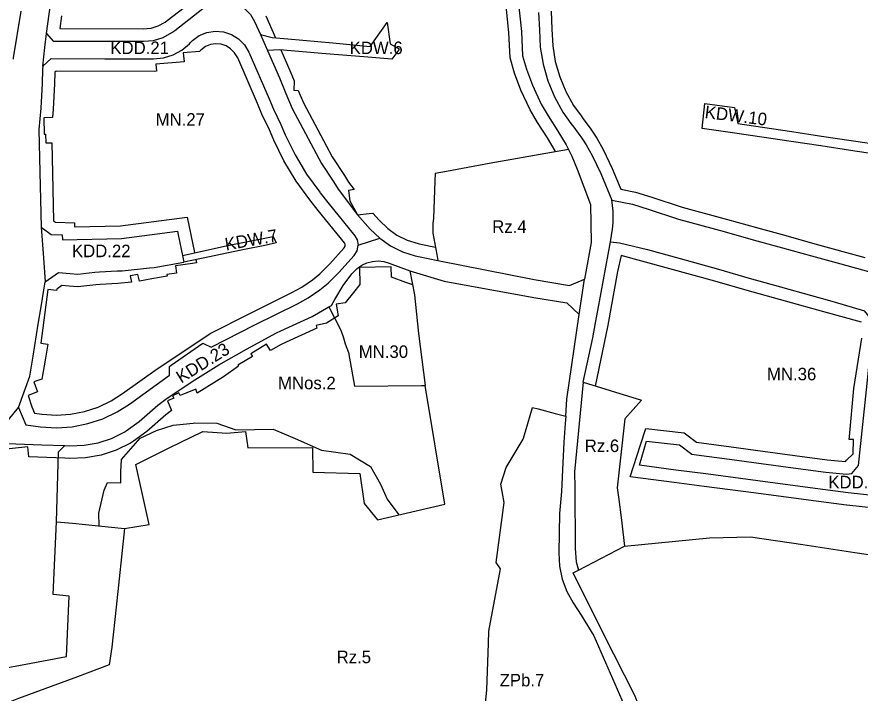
# Model space of a CAD drawing. Extents: x 7414808 to 7417449, y 5544732 to 5546764.
# Drawn here: x 7415895.6 to 7416232.5, y 5545469 to 5545739 of the extents above; entities that cross this region are included whole.
import ezdxf

# ---------------------------------------------------------------- set-up
doc = ezdxf.new("R2010")
doc.units = 0
for name, color, linetype in [('LIN_Linie Rozgraniczajace', 7, 'Continuous'), ('LIN_nieprzekraczale linie zabudowy', 7, 'Continuous'), ('TXT_Oznaczenia Przeznaczenia', 7, 'Continuous')]:
    doc.layers.add(name, color=color, linetype=linetype)

msp = doc.modelspace()

# ---------------------------------------------------------------- linework, layer by layer
at = {"layer": 'LIN_Linie Rozgraniczajace'}
for p, q in [((7415992.94, 5545731.87), (7415995.76, 5545725.48)), ((7416120.04, 5545518.08), (7416138.44, 5545527.72))]:
    msp.add_line(p, q, dxfattribs=at)
for points in [[(7415907.51, 5545732.31), (7415908.48, 5545740.08), (7415910.18, 5545751.57), (7415912.74, 5545763.6), (7415920.96, 5545779.17), (7415933.01, 5545796.09), (7415954.12, 5545809.43), (7415968.5, 5545818.52)], [(7416081.41, 5545803.58), (7416088.85, 5545770.68), (7416091.67, 5545762.78), (7416096.02, 5545744.11), (7416097.23, 5545733.11), (7416097.68, 5545723.46), (7416099.22, 5545718.1), (7416101.6, 5545711.67), (7416105.11, 5545704.09), (7416107.85, 5545699.39), (7416111.82, 5545693.27), (7416115.05, 5545687.84), (7416115.96, 5545686.02)], [(7415907.51, 5545732.31), (7415910.16, 5545729.3), (7415930.83, 5545729.24), (7415946.27, 5545729.2), (7415950.24, 5545729.58), (7415954.06, 5545730.75), (7415957.57, 5545732.66), (7415958.68, 5545733.47), (7415969.92, 5545742.3), (7415971.21, 5545743.2), (7415974.2, 5545744.56), (7415975.03, 5545744.8), (7415981.8, 5545744.72), (7415983.83, 5545743.99), (7415986.63, 5545742.29), (7415988.94, 5545739.96), (7415990.61, 5545737.14), (7415992.94, 5545731.87)], [(7415894.25, 5545722.05), (7415894.28, 5545722.62), (7415897.34, 5545741.25)], [(7416104.08, 5545740.7), (7416104.41, 5545733.79), (7416104.74, 5545726.87), (7416105.87, 5545720.04), (7416107.77, 5545713.38), (7416110.44, 5545706.99), (7416113.82, 5545700.94), (7416117.01, 5545696.41), (7416118.2, 5545694.88), (7416120.58, 5545691.64), (7416121.36, 5545690.5), (7416123.1, 5545687.87), (7416125.49, 5545683.65), (7416128.92, 5545676.42), (7416133.31, 5545665.82)], [(7415992.94, 5545731.87), (7415997.64, 5545730.76), (7416003.92, 5545730.2), (7416021.81, 5545728.58), (7416036.8, 5545727.18), (7416043.6, 5545736.66), (7416044.74, 5545728.23), (7416048.4, 5545726.18), (7416048.18, 5545725.86), (7416045.41, 5545722.1), (7416034.23, 5545722.95), (7416019.07, 5545724.21), (7416000.57, 5545725.85), (7415995.76, 5545725.48)], [(7415906.01, 5545719.31), (7415909.35, 5545722.3), (7415930.81, 5545722.24), (7415950.21, 5545722.19), (7415954.19, 5545722.57), (7415958.01, 5545723.74), (7415961.52, 5545725.65), (7415964.58, 5545728.21), (7415965.05, 5545728.71), (7415965.8, 5545729.47), (7415968.49, 5545731.46), (7415971.57, 5545732.75), (7415974.87, 5545733.27), (7415978.2, 5545733), (7415981.37, 5545731.95), (7415984.2, 5545730.17), (7415986.53, 5545727.78), (7415988.36, 5545724.9), (7415996.39, 5545706.26), (7415998.11, 5545702.13), (7416001.08, 5545695.98), (7416002.85, 5545691.87), (7416006.75, 5545683.83), (7416011.35, 5545676.16), (7416016.62, 5545668.93), (7416016.77, 5545668.75), (7416019.93, 5545664.82), (7416030.61, 5545651.54), (7416031.54, 5545649.91), (7416031.93, 5545647.77)], [(7415906.01, 5545719.31), (7415906.81, 5545726.71), (7415907.51, 5545732.31)], [(7415995.76, 5545725.48), (7416000.49, 5545714.59), (7416003.1, 5545708.38), (7416005.56, 5545702.43), (7416017.36, 5545680.48), (7416022.29, 5545672.95), (7416024.05, 5545670.17), (7416031.71, 5545659.93), (7416036.79, 5545654.26), (7416040.61, 5545650.6)], [(7415906.01, 5545719.31), (7415905.88, 5545718.11), (7415905.67, 5545712.39), (7415905.16, 5545702.5), (7415904.35, 5545694.05), (7415904.73, 5545682.51), (7415905.3, 5545655)], [(7416244.61, 5545680.15), (7416241.27, 5545683.73), (7416228.65, 5545685.63), (7416216.78, 5545687.41), (7416205.02, 5545689.19), (7416193.25, 5545690.95), (7416181.49, 5545692.72), (7416169.38, 5545694.4), (7416170.52, 5545704.42), (7416182.37, 5545702.72), (7416183.62, 5545696.43), (7416193.51, 5545694.94), (7416205.3, 5545693.18), (7416217.13, 5545691.4), (7416228.92, 5545689.63), (7416241.72, 5545687.7), (7416245.78, 5545690.76)], [(7416115.96, 5545686.02), (7416084.34, 5545680.43), (7416067.33, 5545677.18), (7416062.7, 5545676.44), (7416062.68, 5545673.5), (7416062.05, 5545658.41), (7416061.78, 5545656.61), (7416061.87, 5545652.66), (7416063.42, 5545644.09), (7416063.85, 5545641.74)], [(7416115.96, 5545686.02), (7416117.31, 5545683.34), (7416119.5, 5545678.13), (7416124.85, 5545664.06), (7416125.08, 5545648.83), (7416122.42, 5545634.18)], [(7416132.78, 5545649.12), (7416133.25, 5545651.66), (7416133.63, 5545654.21), (7416133.85, 5545656.79), (7416133.91, 5545659.07), (7416133.83, 5545661.34), (7416133.63, 5545663.59), (7416133.47, 5545664.81), (7416133.31, 5545665.82)], [(7416133.31, 5545665.82), (7416141.6, 5545664.19), (7416147.8, 5545662.19), (7416159.98, 5545658.26), (7416178.16, 5545653.24), (7416189.86, 5545650.01), (7416201.52, 5545646.8), (7416213.15, 5545643.58), (7416224.83, 5545640.35), (7416235.89, 5545637.3)], [(7415905.3, 5545655), (7415906.23, 5545642.79), (7415906.97, 5545633.14)], [(7415905.3, 5545655), (7415908.22, 5545652.88), (7415909.36, 5545652.06), (7415913.78, 5545651.91), (7415913.86, 5545650), (7415937.44, 5545650.49), (7415959.79, 5545653.4), (7415960.08, 5545652.01), (7415961.85, 5545643.74)], [(7415961.85, 5545643.74), (7415977.99, 5545647.24), (7415979.83, 5545647.64), (7415998.05, 5545651.32), (7415999.24, 5545648.8), (7415995.33, 5545647.86), (7415985.18, 5545645.84), (7415969.38, 5545642.54), (7415964.87, 5545641.59), (7415963.69, 5545641.32), (7415962.34, 5545641.07)], [(7416031.93, 5545647.77), (7416040.61, 5545650.6)], [(7416040.61, 5545650.6), (7416044.94, 5545647.55), (7416049.67, 5545645.2), (7416054.7, 5545643.58), (7416056.03, 5545643.29), (7416063.85, 5545641.74)], [(7416121.93, 5545593.1), (7416125.73, 5545610.82), (7416126.85, 5545616.83), (7416128.13, 5545623.87), (7416132.78, 5545649.12)], [(7416132.78, 5545649.12), (7416136.35, 5545648.74), (7416147.54, 5545646.03), (7416160.59, 5545642.54), (7416175.9, 5545638.27), (7416188.25, 5545634.64), (7416200.73, 5545631.21), (7416213.14, 5545627.73), (7416219.41, 5545625.95), (7416225.72, 5545624.16), (7416234.33, 5545621.67)], [(7415896.29, 5545583.07), (7415899.24, 5545576.09), (7415905.12, 5545575.35), (7415911.43, 5545574.96), (7415917.74, 5545575.36), (7415923.95, 5545576.56), (7415929.95, 5545578.54), (7415935.66, 5545581.25), (7415940.61, 5545584.4), (7415956.55, 5545595.89), (7415956.64, 5545599.37), (7415957.32, 5545599.86), (7415969.92, 5545608.63), (7415970.43, 5545608.4), (7415973.22, 5545607.08), (7415990.67, 5545615.99), (7416007.75, 5545624.43), (7416012.07, 5545626.82), (7416016.71, 5545629.99), (7416019.97, 5545632.68), (7416024.25, 5545636.95), (7416030.39, 5545643.76), (7416031.53, 5545645.62), (7416031.93, 5545647.77)], [(7415961.85, 5545643.74), (7415962.34, 5545641.07)], [(7415906.97, 5545633.14), (7415912.22, 5545636.85), (7415916.91, 5545636.49), (7415919.96, 5545636.25), (7415926.73, 5545637.01), (7415928.65, 5545637.11), (7415935.73, 5545637.52), (7415937.64, 5545637.62), (7415948.6, 5545638.71), (7415950.52, 5545638.9), (7415962.34, 5545641.07)], [(7416020.22, 5545623.18), (7416021.27, 5545623.79), (7416022.71, 5545626.13), (7416026.02, 5545631.69), (7416029.52, 5545636.33), (7416029.94, 5545636.86), (7416031.55, 5545638.47), (7416033.42, 5545639.78), (7416035.49, 5545640.73), (7416037.69, 5545641.32), (7416039.96, 5545641.5), (7416042.23, 5545641.29), (7416044.43, 5545640.69), (7416052.69, 5545637.62)], [(7416063.85, 5545641.74), (7416102.37, 5545634.08), (7416116.45, 5545631.75), (7416122.42, 5545634.18)], [(7416052.69, 5545637.62), (7416054.55, 5545628.01), (7416056.12, 5545612.51), (7416058.82, 5545591.82)], [(7416052.69, 5545637.62), (7416066.38, 5545633.39), (7416102.2, 5545626.96), (7416115.39, 5545624.81), (7416120.24, 5545620.14)], [(7415896.29, 5545583.07), (7415900.76, 5545595.5), (7415902.09, 5545603.55), (7415904.19, 5545616.23), (7415905.33, 5545623.22), (7415906.97, 5545633.14)], [(7416120.24, 5545620.14), (7416122.42, 5545634.18)], [(7415914.76, 5545567.8), (7415916.82, 5545567.73), (7415922.47, 5545567.91), (7415928.04, 5545568.89), (7415933.41, 5545570.65), (7415938.49, 5545573.14), (7415939.32, 5545573.71), (7415944.47, 5545577.41), (7415951.99, 5545583.9), (7415955.09, 5545586.35), (7415965.63, 5545593.34), (7415976.38, 5545600.01), (7415987.33, 5545606.33), (7415999.41, 5545612.78), (7416001.07, 5545613.65), (7416013.66, 5545619.33), (7416020.22, 5545623.18)], [(7416020.22, 5545623.18), (7416025.07, 5545613.84), (7416026.11, 5545610.84), (7416026.83, 5545608.44), (7416028.15, 5545604.92), (7416030.56, 5545591.56), (7416057.31, 5545591.81), (7416058.82, 5545591.82)], [(7416114.9, 5545579.52), (7416115.39, 5545586.28), (7416120.24, 5545620.14)], [(7416280.89, 5545539.4), (7416277.26, 5545543.91), (7416253.43, 5545546.19), (7416227.81, 5545548.93), (7416212.54, 5545550.95), (7416191.63, 5545553.73), (7416170.85, 5545556.48), (7416158.95, 5545558.06), (7416144.45, 5545559.95), (7416147.19, 5545569.52), (7416160.31, 5545568.05), (7416165.27, 5545564.36), (7416167.14, 5545564.1), (7416180.3, 5545562.33), (7416192.99, 5545560.63), (7416205.81, 5545558.9), (7416218.8, 5545557.21), (7416227.13, 5545556.4), (7416229.18, 5545556.68), (7416231.92, 5545559.87), (7416235.05, 5545590.12), (7416237.84, 5545617.21), (7416234.33, 5545621.67)], [(7415938.67, 5545534.77), (7415948.54, 5545536.36), (7415943.11, 5545560.3), (7415956.52, 5545566.88), (7415969.93, 5545573.46), (7415979.57, 5545572.79), (7415986.96, 5545573.43), (7415987.85, 5545566.85), (7416013.75, 5545566.99), (7416013.92, 5545557.24), (7416032.64, 5545556.65), (7416034.32, 5545544.64), (7416039.73, 5545538.23), (7416066.65, 5545544.42), (7416058.82, 5545591.82)], [(7416121.93, 5545593.1), (7416118.46, 5545557.34), (7416118.5, 5545550.99), (7416118.63, 5545526.71), (7416119.06, 5545521.44), (7416120.04, 5545518.08)], [(7416121.93, 5545593.1), (7416145.13, 5545585.89), (7416138.59, 5545578.53), (7416135.41, 5545550.99), (7416136.18, 5545546.27), (7416137.06, 5545539.11), (7416138.44, 5545527.72)], [(7415884.74, 5545568.94), (7415896.29, 5545583.07)], [(7416073.13, 5545451.31), (7416082.32, 5545459.31), (7416083.36, 5545470.35), (7416084.04, 5545488.79), (7416084.22, 5545493.67), (7416088.82, 5545518.65), (7416087.12, 5545521.07), (7416090.29, 5545545.12), (7416089.03, 5545552.44), (7416091.1, 5545559), (7416097.95, 5545570.39), (7416098.86, 5545573.49), (7416101.69, 5545583.08), (7416103.92, 5545582.48), (7416110.68, 5545580.67), (7416114.9, 5545579.52)], [(7416114.9, 5545579.52), (7416114.69, 5545576.6), (7416114.12, 5545569.12), (7416113.66, 5545558.17), (7416113.18, 5545549.45), (7416112.43, 5545540.75), (7416112.1, 5545524.93), (7416112.39, 5545519.65), (7416113.47, 5545514.47), (7416115.32, 5545509.52), (7416117.83, 5545505.01), (7416121.06, 5545500.08), (7416126.17, 5545491.83), (7416142.87, 5545453.5), (7416145.64, 5545448.11)], [(7415884.74, 5545568.94), (7415905.6, 5545568.15), (7415914.76, 5545567.8)], [(7415911.47, 5545537.31), (7415912.3, 5545565.33), (7415914.76, 5545567.8)], [(7416138.44, 5545527.72), (7416172.34, 5545530.93), (7416188.69, 5545531.4), (7416209.61, 5545528.27), (7416230.49, 5545525.15), (7416251.4, 5545522.03), (7416262.41, 5545520.38), (7416271.32, 5545519.1), (7416278.32, 5545531.86), (7416280.89, 5545539.4)], [(7415878.92, 5545471.66), (7415879.03, 5545476.77), (7415899.24, 5545480.61), (7415915.42, 5545483.56), (7415916.46, 5545507.74), (7415910.18, 5545508.3), (7415911.47, 5545537.31)], [(7415938.67, 5545534.77), (7415935.27, 5545503.31), (7415933.52, 5545487.35), (7415932.44, 5545480.22), (7415919.83, 5545475.46), (7415896.22, 5545466.89), (7415888.9, 5545463.98), (7415889.93, 5545455.69), (7415891.31, 5545437.02), (7415893.94, 5545421.72), (7415901.72, 5545402.69), (7415907.31, 5545390.02), (7415908.9, 5545386.42), (7415921.31, 5545387.03), (7415938.04, 5545387.87)], [(7415911.47, 5545537.31), (7415917.8, 5545536.79), (7415938.67, 5545534.77)], [(7416203.8, 5545402.25), (7416202.88, 5545403.98), (7416200.74, 5545414.13), (7416199.13, 5545418.37), (7416184.71, 5545425.63), (7416166.06, 5545437.53), (7416157.09, 5545443.81), (7416150.47, 5545450.75), (7416147.44, 5545455.04), (7416142.62, 5545467.78), (7416134.07, 5545484.59), (7416128.45, 5545495.83), (7416117.88, 5545516.95), (7416120.04, 5545518.08)]]:
    msp.add_lwpolyline(points, dxfattribs=at)
at = {"layer": 'LIN_nieprzekraczale linie zabudowy'}
for points in [[(7415913.43, 5545739.4), (7415912.8, 5545734.29), (7415946.03, 5545734.2), (7415949.26, 5545734.51), (7415952.12, 5545735.39), (7415954.89, 5545736.89), (7415955.66, 5545737.46), (7415966.94, 5545746.33)], [(7416110.83, 5545685.11), (7416110.66, 5545685.44), (7416107.57, 5545690.63), (7416103.59, 5545696.77), (7416100.67, 5545701.78), (7416096.98, 5545709.75), (7416094.46, 5545716.54), (7416092.71, 5545722.64), (7416092.24, 5545732.72), (7416091.08, 5545743.27)], [(7416109.06, 5545741.21), (7416109.4, 5545734.03), (7416109.72, 5545727.4), (7416110.75, 5545721.14), (7416112.5, 5545715.03), (7416114.94, 5545709.17), (7416118.05, 5545703.61), (7416121.03, 5545699.39), (7416122.18, 5545697.9), (7416124.66, 5545694.54), (7416125.51, 5545693.29), (7416127.37, 5545690.48), (7416129.93, 5545685.96), (7416133.49, 5545678.45), (7416136.9, 5545670.21), (7416142.85, 5545669.04), (7416149.34, 5545666.95), (7416161.41, 5545663.05), (7416179.49, 5545658.06), (7416191.19, 5545654.83), (7416202.85, 5545651.62), (7416214.48, 5545648.4), (7416234.38, 5545642.9)], [(7415995.07, 5545739.43), (7415997.51, 5545733.89), (7415998.94, 5545730.64)], [(7415967.4, 5545640.74), (7415965.78, 5545640.56), (7415958.95, 5545639.54), (7415959.39, 5545636.6), (7415955.58, 5545636.1), (7415955.7, 5545635.5), (7415949.61, 5545634.41), (7415944.6, 5545633.39), (7415943.99, 5545636.17), (7415940.9, 5545635.54), (7415941.41, 5545633.03), (7415936.01, 5545632.53), (7415928.92, 5545632.12), (7415927.14, 5545632.02), (7415920.04, 5545631.23), (7415916.52, 5545631.51), (7415913.63, 5545631.73), (7415911.56, 5545630.26), (7415911.46, 5545629.67), (7415908.04, 5545630.13), (7415905.18, 5545608.68), (7415907.95, 5545608.31), (7415907.02, 5545602.73), (7415905.62, 5545594.34), (7415902.45, 5545593.3), (7415903.93, 5545589.22), (7415900.19, 5545587.87), (7415901.66, 5545583.22), (7415902.72, 5545580.69), (7415905.59, 5545580.33), (7415911.42, 5545579.97), (7415917.1, 5545580.33), (7415922.68, 5545581.41), (7415928.09, 5545583.19), (7415933.24, 5545585.64), (7415937.81, 5545588.54), (7415951.62, 5545598.5), (7415973.13, 5545612.65), (7415988.42, 5545620.46), (7416005.43, 5545628.87), (7416009.44, 5545631.08), (7416013.7, 5545633.99), (7416016.61, 5545636.39), (7416020.63, 5545640.39), (7416026.37, 5545646.77), (7416026.78, 5545647.45), (7416026.84, 5545647.77), (7416026.77, 5545648.17), (7416026.46, 5545648.71), (7416016.03, 5545661.68), (7416012.65, 5545665.89), (7416007.18, 5545673.39), (7416002.34, 5545681.45), (7415998.3, 5545689.79), (7415996.53, 5545693.9), (7415993.55, 5545700.08), (7415991.79, 5545704.31), (7415983.93, 5545722.55), (7415982.59, 5545724.66), (7415981.04, 5545726.26), (7415979.22, 5545727.39), (7415977.19, 5545728.07), (7415975.06, 5545728.24), (7415972.95, 5545727.9), (7415970.98, 5545727.08), (7415969.09, 5545725.69), (7415968.55, 5545725.13), (7415962.12, 5545724.62), (7415962.4, 5545721.02), (7415951.18, 5545720.13), (7415951.41, 5545717.28), (7415950.45, 5545717.18), (7415911.26, 5545717.3), (7415910.84, 5545716.92), (7415910.67, 5545712.17), (7415910.15, 5545702.13), (7415909.82, 5545698.76), (7415906.44, 5545698.69), (7415906.55, 5545692.09), (7415907.06, 5545692.1), (7415907.13, 5545688.68), (7415909.53, 5545688.71), (7415909.73, 5545682.64), (7415910.25, 5545657.59), (7415911.05, 5545657.01), (7415918.59, 5545656.75), (7415918.65, 5545655.1), (7415937.06, 5545655.48), (7415963.71, 5545658.95), (7415966.55, 5545644.92)], [(7416001.07, 5545725.81), (7416005.09, 5545716.56), (7416006.44, 5545713.46), (7416006.23, 5545709.71), (7416008.01, 5545709.61), (7416010.08, 5545704.58), (7416021.66, 5545683.04), (7416026.49, 5545675.66), (7416028.17, 5545673.01), (7416030.43, 5545669.99), (7416028.16, 5545669.67), (7416028.61, 5545665.57), (7416031.71, 5545659.93), (7416036.42, 5545660.49), (7416037.79, 5545660.66), (7416040.39, 5545657.74), (7416043.8, 5545654.47), (7416047.5, 5545651.86), (7416051.56, 5545649.84), (7416056.01, 5545648.42), (7416057.06, 5545648.19), (7416062.89, 5545647.03)], [(7415967.13, 5545642.07), (7415967.4, 5545640.74)], [(7416233.07, 5545617.06), (7416218.04, 5545621.14), (7416187.39, 5545629.69), (7416174.49, 5545633.47), (7416137, 5545643.73), (7416135.57, 5545637.27), (7416131.77, 5545615.93), (7416126.71, 5545591.55)], [(7416053.77, 5545632.05), (7416051.08, 5545632.88), (7416045.28, 5545634.99), (7416045.15, 5545639.15), (7416032.55, 5545638.91), (7416032.63, 5545632.15), (7416030.17, 5545628.9), (7416026.76, 5545624.76), (7416023.21, 5545624.24), (7416024.04, 5545619.59), (7416019.35, 5545616.68), (7416015.21, 5545615.75), (7416015.48, 5545614.67), (7416003.25, 5545609.15), (7416001.21, 5545608.1), (7415996.9, 5545605.78), (7415995.31, 5545608.29), (7415989.13, 5545604.45), (7415989.75, 5545603.36), (7415983.9, 5545599.91), (7415984.18, 5545599.47), (7415978.16, 5545595.27), (7415967.69, 5545588.71), (7415967.06, 5545590.27), (7415960.8, 5545587.74), (7415960.37, 5545588.81), (7415957.8, 5545587.69), (7415958.27, 5545586.69), (7415955.75, 5545585.63), (7415957.42, 5545581.8), (7415955.16, 5545580.04), (7415947.57, 5545573.48), (7415942.19, 5545569.62), (7415941.01, 5545568.81), (7415935.3, 5545566), (7415929.25, 5545564.03), (7415922.99, 5545562.93), (7415916.81, 5545562.72), (7415914.8, 5545562.8), (7415900.45, 5545563.34), (7415900.02, 5545567.35), (7415880.29, 5545565.23)], [(7416252.9, 5545541.22), (7416227.28, 5545543.96), (7416227.15, 5545543.97), (7416211.88, 5545545.99), (7416190.97, 5545548.77), (7416190.97, 5545548.77), (7416170.19, 5545551.52), (7416158.29, 5545553.1), (7416158.3, 5545553.1), (7416140.64, 5545555.4), (7416144.74, 5545568.08), (7416146.87, 5545574.66), (7416162.21, 5545572.87), (7416167.23, 5545569.13), (7416180.97, 5545567.29), (7416180.96, 5545567.29), (7416193.65, 5545565.59), (7416206.46, 5545563.86), (7416219.36, 5545562.18), (7416226.7, 5545561.47), (7416227.11, 5545561.94), (7416229.71, 5545564.48), (7416229.86, 5545570.21), (7416228.2, 5545570.26), (7416228.36, 5545571.45), (7416230.08, 5545590.63), (7416233.27, 5545610.66)], [(7415928.56, 5545535.75), (7415928.35, 5545540.85), (7415930.51, 5545550.05), (7415931.87, 5545553.01), (7415937.13, 5545552.9), (7415937.12, 5545557.35), (7415937.36, 5545562.31), (7415944.94, 5545570.82), (7415951.41, 5545573.77), (7415958.12, 5545575.91), (7415966.08, 5545576.77), (7415966.66, 5545576.83), (7415975.58, 5545576.7), (7415975.58, 5545576.7), (7415975.58, 5545576.7), (7415983.07, 5545574.13), (7415998.03, 5545574.37), (7416006.79, 5545570.7), (7416017.27, 5545565.94), (7416028.8, 5545564.41), (7416036.95, 5545559.4), (7416040.89, 5545552.41), (7416043.61, 5545546.46), (7416048.19, 5545540.18)]]:
    msp.add_lwpolyline(points, dxfattribs=at)

# ---------------------------------------------------------------- texts
at = {"layer": 'TXT_Oznaczenia Przeznaczenia'}
for s, p in [('KDD.21', (7415932.98, 5545724.1)), ('KDW.6', (7416028.59, 5545724.1)), ('MN.27', (7415951.07, 5545695.51)), ('Rz.4', (7416085.55, 5545652.72)), ('KDD.22', (7415917.63, 5545643.02)), ('MN.30', (7416032.23, 5545602.81)), ('MN.36', (7416195.33, 5545593.86)), ('MNos.2', (7415999.98, 5545590.3)), ('Rz.6', (7416122.52, 5545565.23)), ('KDD.27', (7416219.84, 5545550.75)), ('Rz.5', (7416023.39, 5545480.94)), ('ZPb.7', (7416088.52, 5545471.68))]:
    msp.add_text(s, height=5, dxfattribs=at).set_placement(p)
for s, rotation, p in [('KDW.10', 352.8423, (7416170.28, 5545698.61)), ('KDW.7', 10, (7415979.2, 5545645.67)), ('KDD.23', 32, (7415961.27, 5545592.53))]:
    msp.add_text(s, height=5, rotation=rotation, dxfattribs=at).set_placement(p)

doc.saveas('drawing.dxf')
